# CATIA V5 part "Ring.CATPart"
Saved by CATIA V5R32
Part number: Part1.1
Bounding box of the stored display mesh (mm): x -5 to 5, y -15 to 15, z -15 to 15
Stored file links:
  D:\PROJECTS\Project 2022\CATIA V5 6R 2022\Resources\Part Files\c12_catia_v5_6r2022_prt\c12_catia_v5-6r2022 figr_12-15\Ring.CATPart
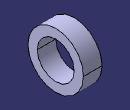
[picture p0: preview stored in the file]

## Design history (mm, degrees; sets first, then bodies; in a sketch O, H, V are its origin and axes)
Body1 (main body)
  Sketch1 on yz-plane, origin (0, 0, 0), H (0, 1, 0), V (0, 0, 1)
    circle A1 centre (0, 0) radius 15
    circle A2 centre (0, 0) radius 10
    radius A1 = 15
    radius A2 = 10
  Pad1: profile Sketch1, direction (1, 0, 0), length 5, mirrored extent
